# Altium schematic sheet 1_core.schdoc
size 431 x 309 mm; Symbol: Sheet-Symbol_A4; Device: Sheet-Symbol_A4; Company: 嘉立创EDA; Version: V1.0; Page Size: A4; @Project Name: fm33; @Page Count: 3; @Update Date: 2025-07-19; @Create Date: 2025-07-03; @Schematic Name: Schematic6; @Page No: 1; @Page Name: core; Title Block Position: 3; Width: 1655; Height: 1170; Region Start: 1; X Region Count: 6; Y Region Count: 4; Blade Width: 10; @Board Name: core_3; @Create Time: 03:54:39; @Update Time: 14:12:30
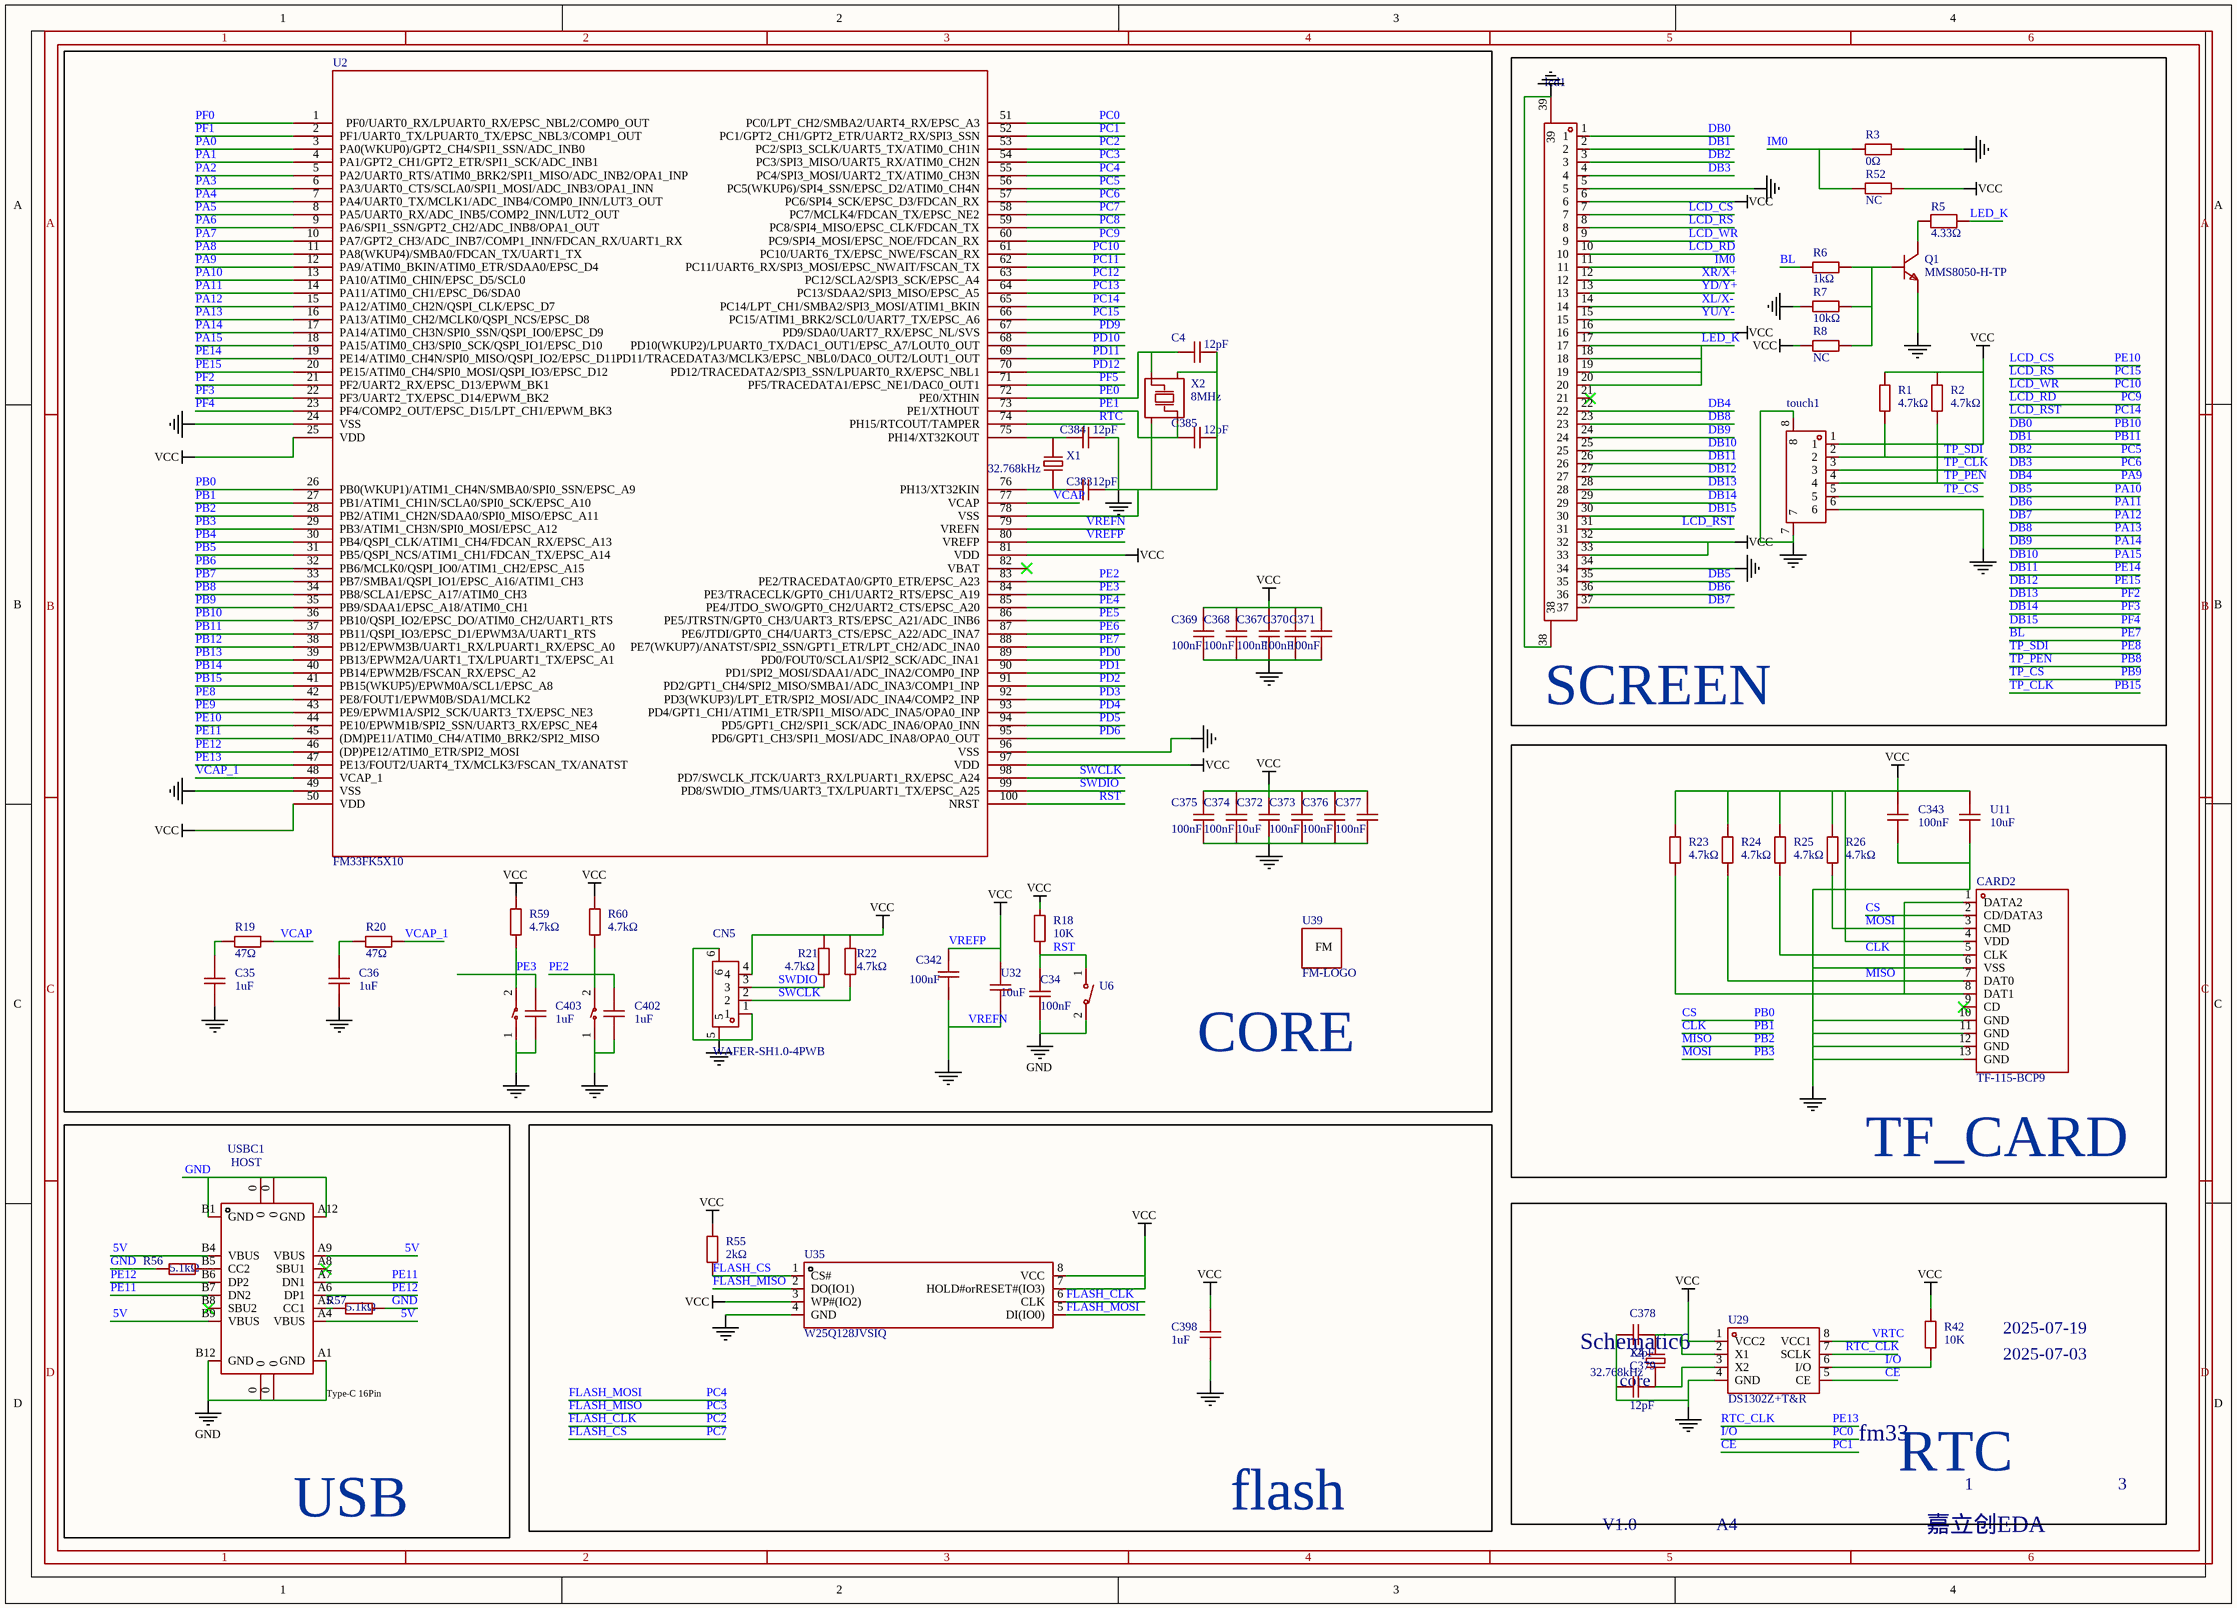
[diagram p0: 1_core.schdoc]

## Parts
C4  12pF  [C0402-NSK]  (value not drawn)
C34  100nF  [C0402-NSK]
C35  1uF  [C0402-NSK]  (value not drawn)
C36  1uF  [C0402-NSK]  (value not drawn)
C342  100nF  [C0402-NSK]  (value not drawn)
C343  100nF  [C0402-NSK]  (value not drawn)
C367  100nF  [C0402-NSK]  (value not drawn)
C368  100nF  [C0402-NSK]  (value not drawn)
C369  100nF  [C0402-NSK]  (value not drawn)
C370  100nF  [C0402-NSK]  (value not drawn)
C371  100nF  [C0402-NSK]  (value not drawn)
C372  10uF  [C0402-NSK]  (value not drawn)
C373  100nF  [C0402-NSK]  (value not drawn)
C374  100nF  [C0402-NSK]  (value not drawn)
C375  100nF  [C0402-NSK]  (value not drawn)
C376  100nF  [C0402-NSK]  (value not drawn)
C377  100nF  [C0402-NSK]  (value not drawn)
C378  12pF  [C0402-NSK]  (value not drawn)
C379  12pF  [C0402-NSK]  (value not drawn)
C383  12pF  [C0402-NSK]  (value not drawn)
C384  12pF  [C0402-NSK]  (value not drawn)
C385  12pF  [C0402-NSK]  (value not drawn)
C398  1uF  [C0603 NSK]
C402  1uF  [C0402-NSK]  (value not drawn)
C403  1uF  [C0402-NSK]  (value not drawn)
CARD2  TF-115-BCP9  [TF-SMD_TF-115-BCP9]  (value not drawn)
CN5  WAFER-SH1.0-4PWB  [CONN-SMD_4P-P1.00_WAFER-SH1.0-4PWB]  (value not drawn)
lcd1  KH-FG0.5-H2.0-37PIN  [FPC-SMD_37P-P0.50_KINGHELM_KH-FG0.5-H2.0-37PIN]  (value not drawn)
Q1  MMS8050-H-TP  [SOT-23-3_L2.9-W1.3-P1.90-LS2.4-BR]  (value not drawn)
R1  4.7kΩ  [R0402]  (value not drawn)
R2  4.7kΩ  [R0402]  (value not drawn)
R3  0Ω  [R0402]  (value not drawn)
R5  4.33Ω  [C0603]  (value not drawn)
R6  1kΩ  [R0402]  (value not drawn)
R7  10kΩ  [R0402]  (value not drawn)
R8  NC  [R0402]  (value not drawn)
R18  10K  [R0402]
R19  47Ω  [R0402]  (value not drawn)
R20  47Ω  [R0402]  (value not drawn)
R21  4.7kΩ  [R0402]  (value not drawn)
R22  4.7kΩ  [R0402]  (value not drawn)
R23  4.7kΩ  [R0402]  (value not drawn)
R24  4.7kΩ  [R0402]  (value not drawn)
R25  4.7kΩ  [R0402]  (value not drawn)
R26  4.7kΩ  [R0402]  (value not drawn)
R42  10K  [R0402]
R52  NC  [R0402]  (value not drawn)
R55  2kΩ  [R0402]  (value not drawn)
R56  5.1kΩ  [R0402]  (value not drawn)
R57  5.1kΩ  [R0402]  (value not drawn)
R59  4.7kΩ  [R0402]  (value not drawn)
R60  4.7kΩ  [R0402]  (value not drawn)
touch1  FPC-05F-6PH20  [FPC-SMD_6P-P0.50_XUNPU_FPC-05F-6PH20]  (value not drawn)
U2  FM33FK5X10  [LQFP100]  (value not drawn)
U6  TS2306A 200gf 002  [SW-SMD_L3.0-W2.0-LS3.5]  (value not drawn)
U11  10uF  [C0402-NSK]  (value not drawn)
U29  DS1302Z+T&R  [SOIC-8_L4.9-W3.9-P1.27-LS6.0-BL]  (value not drawn)
U32  10uF  [C0402-NSK]  (value not drawn)
U35  W25Q128JVSIQ  [SOIC-8_L5.3-W5.3-P1.27-LS8.0-BL]  (value not drawn)
U37  THAF09-AC-R  [KEY-SMD_L3.9-W2.9-P4.6-LS5.0-W3.6-EH]  (value not drawn)
U38  THAF09-AC-R  [KEY-SMD_L3.9-W2.9-P4.6-LS5.0-W3.6-EH]  (value not drawn)
U39  FM-LOGO  [FM-LOGO]  (value not drawn)
USBC1  HOST  [USB-TYPE-C_16PIN-MALE-TYPE-C-31-M-12]  (value not drawn)
X1  32.768kHz  [OSC-SMD_L3.2-W1.5]  (value not drawn)
X2  8MHz  [CRYSTAL-SMD_4P-L3.2-W2.5-BL]  (value not drawn)
X4  32.768kHz  [OSC-SMD_L3.2-W1.5]  (value not drawn)

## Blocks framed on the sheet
CORE: C4 C34-C36 C342 C367-C377 C383-C385 C402 C403 CN5 R18-R22 R59 R60 U2 U6 U32 U37-U39 X1 X2
SCREEN: lcd1 Q1 R1-R3 R5-R8 R52 touch1
TF_CARD: C343 CARD2 R23-R26 U11
USB: R56 R57 USBC1
flash: C398 R55 U35
RTC: C378 C379 R42 U29 X4

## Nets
GND: C4.2 C34.1 C35.1 C36.1 C342.1 C343.1 C367.1 C368.1 C369.1 C370.1 C371.1 C372.1 C373.1 C374.1 C375.1 C376.1 C377.1 C378.1 C379.1 C383.2 C384.2 C385.2 C398.1 C402.1 C403.1 CARD2.6(VSS) CARD2.10(GND) CARD2.11(GND) CARD2.12(GND) CARD2.13(GND) CN5.1 CN5.5 CN5.6 lcd1.5 lcd1.34 lcd1.38 lcd1.39 Q1.2(E) R3.2 R7.1 R56.1 R57.2 touch1.6 touch1.7 touch1.8 U2.24(VSS) U2.49(VSS) U2.78(VSS) U2.79(VREFN) U2.96(VSS) U6.2(A&apos;) U11.1 U29.4(GND) U32.1 U35.4(GND) U37.1 U38.1 USBC1.0 USBC1.A1(GND) USBC1.A12(GND) USBC1.B1(GND) USBC1.B12(GND) X2.2 X2.4  [also labelled VREFN]
VREFP: C342.2 C343.2 C367.2 C368.2 C369.2 C370.2 C371.2 C372.2 C373.2 C374.2 C375.2 C376.2 C377.2 C398.2 CARD2.4(VDD) CN5.4 lcd1.6 lcd1.16 lcd1.32 lcd1.33 R1.2 R2.2 R8.1 R18.2 R21.2 R22.2 R23.2 R24.2 R25.2 R26.2 R42.2 R52.2 R55.1 R59.2 R60.2 touch1.1 U2.25(VDD) U2.50(VDD) U2.80(VREFP) U2.81(VDD) U2.97(VDD) U11.2 U29.1(VCC2) U32.2 U35.3(WP#(IO2)) U35.7(HOLD#orRESET#(IO3)) U35.8(VCC)  [also labelled VCC]
5V: USBC1.A4(VBUS) USBC1.A9(VBUS) USBC1.B4(VBUS) USBC1.B9(VBUS)
BL: R6.1 U2.88(PE7(WKUP7)/ANATST/SPI2_SSN/GPT1_ETR/LPT_CH2/ADC_INA0)  [also labelled PE7]
CE: U2.52(PC1/GPT2_CH1/GPT2_ETR/UART2_RX/SPI3_SSN) U29.5(CE)  [also labelled PC1]
CLK: CARD2.5(CLK) R25.1 U2.27(PB1/ATIM1_CH1N/SCLA0/SPI0_SCK/EPSC_A10)  [also labelled PB1]
CS: CARD2.2(CD/DATA3) U2.26(PB0(WKUP1)/ATIM1_CH4N/SMBA0/SPI0_SSN/EPSC_A9)  [also labelled PB0]
DB0: lcd1.1 U2.36(PB10/QSPI_IO2/EPSC_DO/ATIM0_CH2/UART1_RTS)  [also labelled PB10]
DB1: lcd1.2 U2.37(PB11/QSPI_IO3/EPSC_D1/EPWM3A/UART1_RTS)  [also labelled PB11]
DB2: lcd1.3 U2.56(PC5(WKUP6)/SPI4_SSN/EPSC_D2/ATIM0_CH4N)  [also labelled PC5]
DB3: lcd1.4 U2.57(PC6/SPI4_SCK/EPSC_D3/FDCAN_RX)  [also labelled PC6]
DB4: lcd1.22 U2.12(PA9/ATIM0_BKIN/ATIM0_ETR/SDAA0/EPSC_D4)  [also labelled PA9]
DB5: lcd1.35 U2.13(PA10/ATIM0_CHIN/EPSC_D5/SCL0)  [also labelled PA10]
DB6: lcd1.36 U2.14(PA11/ATIM0_CH1/EPSC_D6/SDA0)  [also labelled PA11]
DB7: lcd1.37 U2.15(PA12/ATIM0_CH2N/QSPI_CLK/EPSC_D7)  [also labelled PA12]
DB8: lcd1.23 U2.16(PA13/ATIM0_CH2/MCLK0/QSPI_NCS/EPSC_D8)  [also labelled PA13]
DB9: lcd1.24 U2.17(PA14/ATIM0_CH3N/SPI0_SSN/QSPI_IO0/EPSC_D9)  [also labelled PA14]
DB10: lcd1.25 U2.18(PA15/ATIM0_CH3/SPI0_SCK/QSPI_IO1/EPSC_D10)  [also labelled PA15]
DB11: lcd1.26 U2.19(PE14/ATIM0_CH4N/SPI0_MISO/QSPI_IO2/EPSC_D11)  [also labelled PE14]
DB12: lcd1.27 U2.20(PE15/ATIM0_CH4/SPI0_MOSI/QSPI_IO3/EPSC_D12)  [also labelled PE15]
DB13: lcd1.28 U2.21(PF2/UART2_RX/EPSC_D13/EPWM_BK1)  [also labelled PF2]
DB14: lcd1.29 U2.22(PF3/UART2_TX/EPSC_D14/EPWM_BK2)  [also labelled PF3]
DB15: lcd1.30 U2.23(PF4/COMP2_OUT/EPSC_D15/LPT_CH1/EPWM_BK3)  [also labelled PF4]
FLASH_CLK: U2.53(PC2/SPI3_SCLK/UART5_TX/ATIM0_CH1N) U35.6(CLK)  [also labelled PC2]
FLASH_CS: R55.2 U2.58(PC7/MCLK4/FDCAN_TX/EPSC_NE2) U35.1(CS#)  [also labelled PC7]
FLASH_MISO: U2.54(PC3/SPI3_MISO/UART5_RX/ATIM0_CH2N) U35.2(DO(IO1))  [also labelled PC3]
FLASH_MOSI: U2.55(PC4/SPI3_MOSI/UART2_TX/ATIM0_CH3N) U35.5(DI(IO0))  [also labelled PC4]
I/O: R42.1 U2.51(PC0/LPT_CH2/SMBA2/UART4_RX/EPSC_A3) U29.6(I/O)  [also labelled PC0]
IM0: lcd1.11 R3.1 R52.1
LCD_CS: lcd1.7 U2.44(PE10/EPWM1B/SPI2_SSN/UART3_RX/EPSC_NE4)  [also labelled PE10]
LCD_RD: lcd1.10 U2.60(PC9/SPI4_MOSI/EPSC_NOE/FDCAN_RX)  [also labelled PC9]
LCD_RS: lcd1.8 U2.66(PC15/ATIM1_BRK2/SCL0/UART7_TX/EPSC_A6)  [also labelled PC15]
LCD_RST: lcd1.31 U2.65(PC14/LPT_CH1/SMBA2/SPI3_MOSI/ATIM1_BKIN)  [also labelled PC14]
LCD_WR: lcd1.9 U2.61(PC10/UART6_TX/EPSC_NWE/FSCAN_RX)  [also labelled PC10]
LED_K: lcd1.17 lcd1.18 lcd1.19 lcd1.20 R5.2
MISO: CARD2.7(DAT0) R24.1 U2.28(PB2/ATIM1_CH2N/SDAA0/SPI0_MISO/EPSC_A11)  [also labelled PB2]
MOSI: CARD2.3(CMD) R26.1 U2.29(PB3/ATIM1_CH3N/SPI0_MOSI/EPSC_A12)  [also labelled PB3]
PA0: U2.3(PA0(WKUP0)/GPT2_CH4/SPI1_SSN/ADC_INB0)
PA1: U2.4(PA1/GPT2_CH1/GPT2_ETR/SPI1_SCK/ADC_INB1)
PA2: U2.5(PA2/UART0_RTS/ATIM0_BRK2/SPI1_MISO/ADC_INB2/OPA1_INP)
PA3: U2.6(PA3/UART0_CTS/SCLA0/SPI1_MOSI/ADC_INB3/OPA1_INN)
PA4: U2.7(PA4/UART0_TX/MCLK1/ADC_INB4/COMP0_INN/LUT3_OUT)
PA5: U2.8(PA5/UART0_RX/ADC_INB5/COMP2_INN/LUT2_OUT)
PA6: U2.9(PA6/SPI1_SSN/GPT2_CH2/ADC_INB8/OPA1_OUT)
PA7: U2.10(PA7/GPT2_CH3/ADC_INB7/COMP1_INN/FDCAN_RX/UART1_RX)
PA8: U2.11(PA8(WKUP4)/SMBA0/FDCAN_TX/UART1_TX)
PB4: U2.30(PB4/QSPI_CLK/ATIM1_CH4/FDCAN_RX/EPSC_A13)
PB5: U2.31(PB5/QSPI_NCS/ATIM1_CH1/FDCAN_TX/EPSC_A14)
PB6: U2.32(PB6/MCLK0/QSPI_IO0/ATIM1_CH2/EPSC_A15)
PB7: U2.33(PB7/SMBA1/QSPI_IO1/EPSC_A16/ATIM1_CH3)
PB8: R2.1 touch1.4 U2.34(PB8/SCLA1/EPSC_A17/ATIM0_CH3)  [also labelled TP_PEN]
PB9: touch1.5 U2.35(PB9/SDAA1/EPSC_A18/ATIM0_CH1)  [also labelled TP_CS]
PB12: U2.38(PB12/EPWM3B/UART1_RX/LPUART1_RX/EPSC_A0)
PB13: U2.39(PB13/EPWM2A/UART1_TX/LPUART1_TX/EPSC_A1)
PB14: U2.40(PB14/EPWM2B/FSCAN_RX/EPSC_A2)
PB15: touch1.3 U2.41(PB15(WKUP5)/EPWM0A/SCL1/EPSC_A8)  [also labelled TP_CLK]
PC8: U2.59(PC8/SPI4_MISO/EPSC_CLK/FDCAN_TX)
PC11: U2.62(PC11/UART6_RX/SPI3_MOSI/EPSC_NWAIT/FSCAN_TX)
PC12: U2.63(PC12/SCLA2/SPI3_SCK/EPSC_A4)
PC13: U2.64(PC13/SDAA2/SPI3_MISO/EPSC_A5)
PD0: U2.89(PD0/FOUT0/SCLA1/SPI2_SCK/ADC_INA1)
PD1: U2.90(PD1/SPI2_MOSI/SDAA1/ADC_INA2/COMP0_INP)
PD2: U2.91(PD2/GPT1_CH4/SPI2_MISO/SMBA1/ADC_INA3/COMP1_INP)
PD3: U2.92(PD3(WKUP3)/LPT_ETR/SPI2_MOSI/ADC_INA4/COMP2_INP)
PD4: U2.93(PD4/GPT1_CH1/ATIM1_ETR/SPI1_MISO/ADC_INA5/OPA0_INP)
PD5: U2.94(PD5/GPT1_CH2/SPI1_SCK/ADC_INA6/OPA0_INN)
PD6: U2.95(PD6/GPT1_CH3/SPI1_MOSI/ADC_INA8/OPA0_OUT)
PD9: U2.67(PD9/SDA0/UART7_RX/EPSC_NL/SVS)
PD10: U2.68(PD10(WKUP2)/LPUART0_TX/DAC1_OUT1/EPSC_A7/LOUT0_OUT)
PD11: U2.69(PD11/TRACEDATA3/MCLK3/EPSC_NBL0/DAC0_OUT2/LOUT1_OUT)
PD12: U2.70(PD12/TRACEDATA2/SPI3_SSN/LPUART0_RX/EPSC_NBL1)
PE0: C4.1 U2.72(PE0/XTHIN) X2.3
PE1: C385.1 U2.73(PE1/XTHOUT) X2.1
PE2: C402.2 R60.1 U2.83(PE2/TRACEDATA0/GPT0_ETR/EPSC_A23) U38.2
PE3: C403.2 R59.1 U2.84(PE3/TRACECLK/GPT0_CH1/UART2_RTS/EPSC_A19) U37.2
PE4: U2.85(PE4/JTDO_SWO/GPT0_CH2/UART2_CTS/EPSC_A20)
PE5: U2.86(PE5/JTRSTN/GPT0_CH3/UART3_RTS/EPSC_A21/ADC_INB6)
PE6: U2.87(PE6/JTDI/GPT0_CH4/UART3_CTS/EPSC_A22/ADC_INA7)
PE8: R1.1 touch1.2 U2.42(PE8/FOUT1/EPWM0B/SDA1/MCLK2)  [also labelled TP_SDI]
PE9: U2.43(PE9/EPWM1A/SPI2_SCK/UART3_TX/EPSC_NE3)
PE11: U2.45((DM)PE11/ATIM0_CH4/ATIM0_BRK2/SPI2_MISO) USBC1.A7(DN1) USBC1.B7(DN2)
PE12: U2.46((DP)PE12/ATIM0_ETR/SPI2_MOSI) USBC1.A6(DP1) USBC1.B6(DP2)
PE13: U2.47(PE13/FOUT2/UART4_TX/MCLK3/FSCAN_TX/ANATST) U29.7(SCLK)  [also labelled RTC_CLK]
PF0: U2.1(PF0/UART0_RX/LPUART0_RX/EPSC_NBL2/COMP0_OUT)
PF1: U2.2(PF1/UART0_TX/LPUART0_TX/EPSC_NBL3/COMP1_OUT)
PF5: U2.71(PF5/TRACEDATA1/EPSC_NE1/DAC0_OUT1)
RST: C34.2 R18.1 U2.100(NRST) U6.1(A)
RTC: U2.74(PH15/RTCOUT/TAMPER)
SWCLK: CN5.2 R22.1 U2.98(PD7/SWCLK_JTCK/UART3_RX/LPUART1_RX/EPSC_A24)
SWDIO: CN5.3 R21.1 U2.99(PD8/SWDIO_JTMS/UART3_TX/LPUART1_TX/EPSC_A25)
VCAP: R19.2 U2.77(VCAP)
VCAP_1: R20.2 U2.48(VCAP_1)
VRTC: U29.8(VCC1)
XL/X-: lcd1.14
XR/X+: lcd1.12
YD/Y+: lcd1.13
YU/Y-: lcd1.15
NetC35_2: C35.2 R19.1
NetC36_2: C36.2 R20.1
NetC378_2: C378.2 U29.2(X1) X4.2
NetC379_2: C379.2 U29.3(X2) X4.1
NetC383_1: C383.1 U2.76(PH13/XT32KIN) X1.1
NetC384_1: C384.1 U2.75(PH14/XT32KOUT) X1.2
NetCARD2_1: CARD2.1(DATA2) CARD2.8(DAT1) R23.1
NetQ1_1: Q1.1(B) R6.2 R7.2 R8.2
NetQ1_3: Q1.3(C) R5.1
NetR56_2: R56.2 USBC1.B5(CC2)
NetR57_1: R57.1 USBC1.A5(CC1)

Not connected (* = marked no-connect by the designer): CARD2 9(CD)*; lcd1 21*; U2 82(VBAT)*; USBC1 A8(SBU1)* B8(SBU2)*

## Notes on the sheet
- (near USBC1) Type-C 16Pin

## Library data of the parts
C4 C378 C379 C383-C385 = GRM1555C1H120JA01D: 容值:12pF;精度:±5%;额定电压:50V;材质(温度系数):C0G;; Manufacturer: muRata(村田); Add into BOM: yes; Tolerance: ±5%; Voltage Rated: 50V; Temperature Coefficient: C0G
C34 = CAP_0402: Symbol: CapAcitance; Convert to PCB: yes
C35 C36 C402 C403 = CL05A105KA5NQNC: 容值:1uF;精度:±10%;额定电压:25V;材质(温度系数):X5R;; Manufacturer: SAMSUNG(三星); Add into BOM: yes; Tolerance: ±10%; Voltage Rated: 25V; Temperature Coefficient: X5R
C342 C343 C367-C371 C373-C377 = CL05B104KB54PNC: 容值:100nF;精度:±10%;额定电压:50V;材质(温度系数):X7R;; Manufacturer: SAMSUNG(三星); Add into BOM: yes; Tolerance: ±10%; Voltage Rated: 50V; Temperature Coefficient: X7R
C372 = CL05A106MQ5NUNC: 容值:10uF;精度:±20%;额定电压:6.3V;材质(温度系数):X5R;; Manufacturer: SAMSUNG(三星); Add into BOM: yes; Tolerance: ±20%; Voltage Rated: 6.3V; Temperature Coefficient: X5R
C398 = CL10A105KB8NNNC: 容值:1uF;精度:±10%;额定电压:50V;材质(温度系数):X5R;; Manufacturer: SAMSUNG(三星); Add into BOM: yes; Tolerance: ±10%; Voltage Rated: 50V; Temperature Coefficient: X5R
CARD2 = TF-115-BCP9: 卡连接方式:自弹式;卡类型:MicroSD卡(TF卡);连接器类型:卡座;本体最大高度:1.8mm;工作温度范围:-25℃~+85℃;; Manufacturer: XUNPU(讯普); Add into BOM: yes; Card Connection Mode: 自弹式; Connector Type: 卡座; Maximum Body Height: 1.8mm
CN5 = WAFER-SH1.0-4PWB: 插针结构:1x4P;间距:1mm;安装方式:卧贴;参考系列:SH;总PIN数:4P;排数:1;每排PIN数:4;行距:-;额定电流:1A;触头材质:黄铜;触头镀层:-;工作温度:-25℃~+85℃;; Manufacturer: XUNPU(讯普); Add into BOM: yes; Pins Structure: 1x4P; Pitch: 1mm; Reference Series: SH; Number of PINs Per Row: 4; Current Rating: 1A; Voltage Rating: 50V; Plastic Material: LCP; Supplementary Features: 辅助焊脚; Z-Height of the Board: 3.15mm; X-Length of Bottom Edge on Board (Spacing Line): 6.35mm; Y-Width of Bottom Edge on Board: 5.05mm
lcd1 = KH-FG0.5-H2.0-37PIN: 锁定特性:翻盖式;触点类型:下接;触点数量:37P;间距:0.5mm;安装类型:卧贴;工作温度范围:-25℃~+85℃;; Manufacturer: kinghelm(金航标); Add into BOM: yes; Locking Feature: 翻盖式; Number of Contacts: 37P; Pitch: 0.5mm; FFC, FCB Thickness: 0.3mm
Q1 = MMS8050-H-TP: 晶体管类型:NPN;集电极电流(Ic):500mA;集射极击穿电压(Vceo):25V;耗散功率(Pd):300mW;直流电流增益(hFE):120@50mA,1V;; Manufacturer: MCC(美微科); Add into BOM: yes; type: NPN; Current - Collector(Ic): 500mA; Collector - Emitter Voltage VCEO: 25V; Pd - Power Dissipation: 300mW; Transition frequency(fT): 150MHz; Current - Collector Cutoff: 100nA; Vce Saturation(VCE(sat)): 600mV
R1 R2 R7 R8 R23-R26 R59 R60 = 0402WGF1002TCE: 电阻类型:厚膜电阻;阻值:10kΩ;精度:±1%;功率:62.5mW;最大工作电压:50V;温度系数:±100ppm/℃;; Manufacturer: UNI-ROYAL(厚声); Add into BOM: yes; Tolerance: ±1%; Power(Watts): 62.5mW; Overload Voltage (Max): 50V
R3 R52 = 0402WGF0000TCE: 电阻类型:厚膜电阻;阻值:0Ω;精度:±1%;功率:62.5mW;最大工作电压:50V;温度系数:±800ppm/℃;; Manufacturer: UNI-ROYAL(厚声); Add into BOM: yes; Tolerance: ±1%; Power(Watts): 62.5mW; Overload Voltage (Max): 50V
R5 = CR164R33F: 电阻类型:厚膜电阻;阻值:4.33Ω;精度:±1%;功率:100mW;温度系数:±200ppm/℃;; Manufacturer: Meritek; Add into BOM: yes; Tolerance: ±1%; Power(Watts): 100mW
R6 = 0402WGF1001TCE: 电阻类型:厚膜电阻;阻值:1kΩ;精度:±1%;功率:62.5mW;最大工作电压:50V;温度系数:±100ppm/℃;; Manufacturer: UNI-ROYAL(厚声); Add into BOM: yes; Tolerance: ±1%; Power(Watts): 62.5mW; Overload Voltage (Max): 50V
R18 R42 = Res_0402: Symbol: 电阻; Convert to PCB: yes
R19 R20 = RC0402FR-0747RL: 电阻类型:厚膜电阻;阻值:47Ω;精度:±1%;功率:62.5mW;最大工作电压:50V;温度系数:±100ppm/℃;; Manufacturer: YAGEO(国巨); Add into BOM: yes; Tolerance: ±1%; Power(Watts): 62.5mW; Overload Voltage (Max): 50V
R21 R22 = 0402WGF4701TCE: 电阻类型:厚膜电阻;阻值:4.7kΩ;精度:±1%;功率:62.5mW;最大工作电压:50V;温度系数:±100ppm/℃;; Manufacturer: UNI-ROYAL(厚声); Add into BOM: yes; Tolerance: ±1%; Power(Watts): 62.5mW; Overload Voltage (Max): 50V
R55-R57 = 0402WGF5101TCE: 电阻类型:厚膜电阻;阻值:5.1kΩ;精度:±1%;功率:62.5mW;最大工作电压:50V;温度系数:±100ppm/℃;; Manufacturer: UNI-ROYAL(厚声); Add into BOM: yes; Tolerance: ±1%; Power(Watts): 62.5mW; Overload Voltage (Max): 50V
touch1 = FPC-05F-6PH20: 锁定特性:翻盖式;触点类型:下接;触点数量:6P;间距:0.5mm;安装类型:卧贴;工作温度范围:-25℃~+85℃;; Manufacturer: XUNPU(讯普); Add into BOM: yes; Locking Feature: 翻盖式; Number of Contacts: 6P; Pitch: 0.5mm; FFC, FCB Thickness: 0.3mm
U2 = FM33FK5X10: Add into BOM: yes
U6 = TS2306A 200gf 002: 电路结构:单刀单掷;按钮形状:圆形按钮;作用力:200gf;安装方式:立贴;开关长度:3mm;开关宽度:2mm;开关高度:0.6mm;带支架:不带;触点电流:50mA;额定电压(DC):5V;额定功率:0.25W;绝缘电阻:100MΩ;带灯:无;机械寿命:30万次;; Manufacturer: SHOU HAN(首韩); Add into BOM: yes; Circuit: 单刀单掷; Actuator Style: 圆形按钮; Switch Length: 3mm; Switch Width: 2mm; Switch Height: 0.6mm; Strike Gundam: 不带; Contact Current: 50mA; Voltage Rating (DC): 5V; Power Rating: 0.25W; Insulation Resistance: 100MΩ; Actuator/Cap Color: 黄色; With Lamp: 无; Mechanical Life: 30万次
U11 U32 = HGC0402R5106M100NTEJ: 容值:10uF;精度:±20%;额定电压:10V;材质(温度系数):X5R;; Manufacturer: Chinocera(华瓷); Add into BOM: yes; Tolerance: ±20%; Voltage Rated: 10V; Temperature Coefficient: X5R
U29 = DS1302Z+T&R: 接口:SPI;; Manufacturer: ADI(亚德诺)/MAXIM(美信); Symbol: DS1302ZN+; Add into BOM: yes; Interface: SPI; Operating Voltage: 2V~5.5V
U35 = W25Q128JVSIQ_C113767: 接口类型:SPI;存储容量:-;时钟频率(fc):133MHz;; Manufacturer: Winbond(华邦); Add into BOM: yes; Interface: SPI; Clock Frequency: 133MHz; Voltage - Supply: 2.7V~3.6V; Program / Erase Cycles: 100000次; Page Programming Time (Tpp): 3ms
U37 U38 = THAF09-AC-R: 按钮形状:方形按钮;作用力:250gf;开关长度:2.9mm;开关宽度:3.9mm;开关高度:1.5mm;带支架:不带;触点电流:50mA;额定电压(AC):250V;额定电压(DC):12V;绝缘电阻:100mΩ;带灯:无;机械寿命:5万次;; Manufacturer: jianfu(键富); Add into BOM: yes; Actuator Style: 方形按钮; Operating Force: 250gf; Switch Length: 2.9mm; Switch Width: 3.9mm; Switch Height: 1.5mm; Strike Gundam: 不带; Contact Current: 50mA; Voltage Rating (AC): 250V; Voltage Rating (DC): 12V; Insulation Resistance: 100mΩ; Actuator/Cap Color: 黑色; With Lamp: 无; Pin Style: SMD接片; Mechanical Life: 5万次
U39 = FM-LOGO: Symbol: FM; Add into BOM: yes
USBC1 = HOST: Add into BOM: yes
X1 X4 = X321532768KGD2SI: 晶振类型:贴片晶振;频率:32.768kHz;常温频差:±20ppm;外接负载电容:12.5pF;频率稳定度(全温):-;; Manufacturer: YXC(扬兴晶振); Add into BOM: yes; Crystal Type: 贴片晶振; Normal temperature Frequency Tolerance: ±20ppm; External load capacitor: 12.5pF
X2 = TAXM8M4RDBCCT2T: 晶振类型:贴片晶振;频率:8MHz;常温频差:±10ppm;负载电容:10pF;频率稳定度:±15ppm;; Manufacturer: YJX(雅晶鑫); Add into BOM: yes; Normal temperature Frequency Tolerance: ±10ppm; Load Capacitance: 10pF; Frequency Stability: ±15ppm; Equivalent Series Resistance(ESR): 250Ω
